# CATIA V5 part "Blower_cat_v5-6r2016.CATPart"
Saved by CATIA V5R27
Part number: Blower
Bounding box of the stored display mesh (mm): x -55 to 55, y -55 to 55, z -25 to 80.2
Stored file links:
  E:\_Deepak\2017_Deepak\CATIA\Resources\Tutorial Files\Tutorials\c12_catia_v5_6r2015_tut\c12Tut1\Blower_cat_v5-6r2016.CATPart
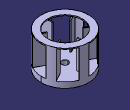
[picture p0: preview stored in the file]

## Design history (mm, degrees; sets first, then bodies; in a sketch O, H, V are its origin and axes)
Body1 (main body)
  Sketch1 on xy-plane, origin (0, 0, 0), H (1, 0, 0), V (0, 1, 0)
    circle A1 centre (0, 0) radius 55
    point P1 (0, 0)
    radius A1 = 55
    coincidence: P1 H, P1 O
  Pad1: profile Sketch1, direction (0, 0, 1), length 12.7
  Sketch2 on face of Pad1, origin (0, 0, 12.7), H (1, 0, 0), V (0, 1, 0)
    line L1 (0, 55) -> (0, 30)
    point P1 (0, 55)
    projected arc E1 centre (0, 0) radius 55 from (18.8111, 51.6831) to (0, 55) ccw from edge of Pad1
    line L2 (2.5, 53.4416) -> (2.5, 30)
    arc A1 centre (0, 0) radius 53.5 from (18.2981, 50.2736) to (2.5, 53.4416) ccw
    line L3 (0, 30) -> (2.5, 30)
    line L4 (18.2981, 50.2736) -> (18.8111, 51.6831)
    length L1 = 25
    distance L1 L2 = 2.5
    distance E1 A1 = 1.5
    angle L4 L1 = 20
    coincidence: P1 V, O L4
    vertical: L1 V
    concentricity: E1 A1
    horizontal: L3 H
  Pad2: profile Sketch2, direction (0, 0, 1), length 65
  CircPattern1: of Pad2, instances 6, angular step 60, axis from face of Pad1 from Sketch1.A1
  Sketch3 on face of Pad1, origin (0, 0, 0), H (1, 0, 0), V (0, -1, 0)
    circle A1 centre (0, 0) radius 15
    radius A1 = 15
  Pad3: profile Sketch3, direction (0, 0, -1), length 25
  Sketch4 on face of Pad2, origin (0, 0, 77.7), H (1, 0, 0), V (0, 1, 0)
    circle A1 centre (0, 0) radius 55
    radius A1 = 55
  Pad4: profile Sketch4, direction (0, 0, 1), length 2.5
  Sketch5 on face of Pad4, origin (0, 0, 80.2), H (1, 0, 0), V (0, 1, 0)
    circle A1 centre (0, 0) radius 40
    circle A2 centre (0, 0) radius 7.5
    radius A2 = 7.5
    radius A1 = 40
  MultiPocket1: profile Sketch5, domains (length 381; length 2.5)
  Sketch6 on yz-plane, origin (0, 0, 0), H (0, 1, 0), V (0, 0, 1)
    line L1 (0, 3.7002) -> (0, 148.5199)
    point P1 (0, 3.7002)
    coincidence: P1 V
    vertical: L1 V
